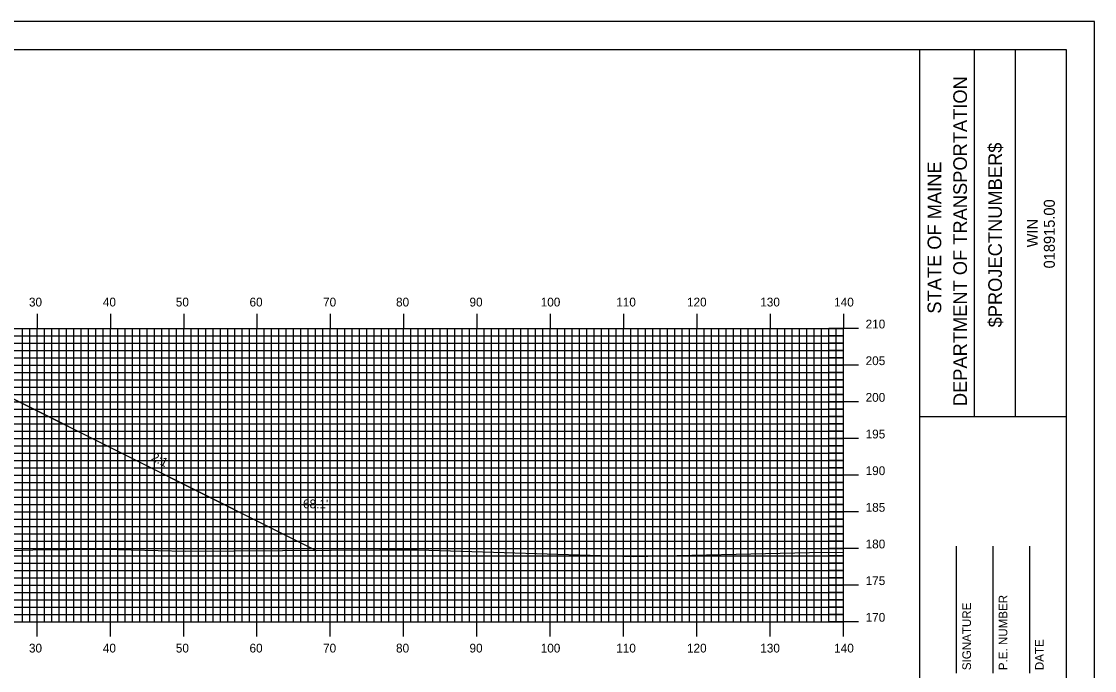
# Model space of a CAD drawing. Extents: x 1809013 to 1809356, y 442591 to 442811.
# Drawn here: x 1809206.2 to 1809352.5, y 442722 to 442810.5 of the extents above; entities that cross this region are included whole.
import ezdxf

# ---------------------------------------------------------------- set-up
doc = ezdxf.new("R2010")
doc.units = 0
for name, color, linetype in [('ANNOTATION', 7, 'Continuous'), ('BORDER', 7, 'Continuous'), ('D_Roadway_Centerline', 7, 'Continuous'), ('D_Roadway_SlopeLines', 7, 'Continuous'), ('D_Text_Standard', 7, 'Continuous'), ('H_V ANNOTATION', 7, 'Continuous'), ('MAJOR', 7, 'Continuous'), ('MINOR', 7, 'Continuous'), ('PLOT BOUNDARY', 7, 'Continuous'), ('S_Roadway_Centerline', 7, 'Continuous')]:
    doc.layers.add(name, color=color, linetype=linetype)

msp = doc.modelspace()

# ---------------------------------------------------------------- linework, layer by layer
at = {"layer": 'BORDER'}
for p, q in [((1809328.72, 442596.67), (1809328.72, 442806.67)), ((1809336.18, 442756.66), (1809336.18, 442806.66)), ((1809341.77, 442756.66), (1809341.77, 442806.66)), ((1809328.73, 442756.65), (1809348.72, 442756.65)), ((1809333.72, 442721.67), (1809333.72, 442738.97)), ((1809338.72, 442721.67), (1809338.72, 442738.97)), ((1809343.72, 442721.67), (1809343.72, 442738.97))]:
    msp.add_line(p, q, dxfattribs=at)
msp.add_lwpolyline([(1809028.72, 442596.67), (1809348.72, 442596.67), (1809348.72, 442806.67), (1809028.72, 442806.67)], close=True, dxfattribs=at)
at = {"layer": 'D_Roadway_Centerline'}
msp.add_lwpolyline([(1809110.51, 442738.65), (1809150.57, 442758.68), (1809155.32, 442761.06), (1809158.32, 442761.18), (1809166.32, 442761.5), (1809178.32, 442761.62), (1809190.32, 442761.38), (1809198.32, 442761.06), (1809201.32, 442760.94), (1809206.07, 442758.57), (1809246.41, 442738.4)], dxfattribs=at)
at = {"layer": 'D_Roadway_SlopeLines'}
msp.add_lwpolyline([(1809201.32, 442760.94), (1809246.41, 442738.4)], dxfattribs=at)
at = {"layer": 'MAJOR'}
for p, q in [((1809208.32, 442770.67), (1809208.32, 442768.67)), ((1809218.32, 442770.67), (1809218.32, 442768.67)), ((1809228.32, 442770.67), (1809228.32, 442768.67)), ((1809238.32, 442770.67), (1809238.32, 442768.67)), ((1809248.32, 442770.67), (1809248.32, 442768.67)), ((1809258.32, 442770.67), (1809258.32, 442768.67)), ((1809268.32, 442770.67), (1809268.32, 442768.67)), ((1809278.32, 442770.67), (1809278.32, 442768.67)), ((1809288.32, 442770.67), (1809288.32, 442768.67)), ((1809298.32, 442770.67), (1809298.32, 442768.67)), ((1809308.32, 442770.67), (1809308.32, 442768.67)), ((1809318.32, 442770.67), (1809318.32, 442768.67)), ((1809038.32, 442768.67), (1809318.32, 442768.67)), ((1809038.32, 442768.67), (1809318.32, 442768.67)), ((1809208.32, 442728.67), (1809208.32, 442768.67)), ((1809218.32, 442728.67), (1809218.32, 442768.67)), ((1809228.32, 442728.67), (1809228.32, 442768.67)), ((1809238.32, 442728.67), (1809238.32, 442768.67)), ((1809248.32, 442728.67), (1809248.32, 442768.67)), ((1809258.32, 442728.67), (1809258.32, 442768.67)), ((1809268.32, 442728.67), (1809268.32, 442768.67)), ((1809278.32, 442728.67), (1809278.32, 442768.67)), ((1809288.32, 442728.67), (1809288.32, 442768.67)), ((1809298.32, 442728.67), (1809298.32, 442768.67)), ((1809308.32, 442728.67), (1809308.32, 442768.67)), ((1809320.33, 442768.67), (1809316.32, 442768.67)), ((1809318.32, 442728.67), (1809318.32, 442768.67)), ((1809318.32, 442728.67), (1809318.32, 442768.67)), ((1809038.32, 442763.67), (1809318.32, 442763.67)), ((1809320.33, 442763.67), (1809316.32, 442763.67)), ((1809038.32, 442758.67), (1809318.32, 442758.67)), ((1809320.33, 442758.67), (1809316.32, 442758.67)), ((1809038.32, 442753.67), (1809318.32, 442753.67)), ((1809320.33, 442753.67), (1809316.32, 442753.67)), ((1809038.32, 442748.67), (1809318.32, 442748.67)), ((1809320.33, 442748.67), (1809316.32, 442748.67)), ((1809038.32, 442743.67), (1809318.32, 442743.67)), ((1809320.33, 442743.67), (1809316.32, 442743.67)), ((1809038.32, 442738.67), (1809318.32, 442738.67)), ((1809320.33, 442738.67), (1809316.32, 442738.67)), ((1809038.32, 442733.67), (1809318.32, 442733.67)), ((1809320.33, 442733.67), (1809316.32, 442733.67)), ((1809038.32, 442728.67), (1809318.32, 442728.67)), ((1809038.32, 442728.67), (1809318.32, 442728.67)), ((1809208.32, 442726.66), (1809208.32, 442728.67)), ((1809218.32, 442726.66), (1809218.32, 442728.67)), ((1809228.32, 442726.66), (1809228.32, 442728.67)), ((1809238.32, 442726.66), (1809238.32, 442728.67)), ((1809248.32, 442726.66), (1809248.32, 442728.67)), ((1809258.32, 442726.66), (1809258.32, 442728.67)), ((1809268.32, 442726.66), (1809268.32, 442728.67)), ((1809278.32, 442726.66), (1809278.32, 442728.67)), ((1809288.32, 442726.66), (1809288.32, 442728.67)), ((1809298.32, 442726.66), (1809298.32, 442728.67)), ((1809308.32, 442726.66), (1809308.32, 442728.67)), ((1809320.33, 442728.67), (1809316.32, 442728.67)), ((1809318.32, 442726.66), (1809318.32, 442728.67))]:
    msp.add_line(p, q, dxfattribs=at)
at = {"layer": 'MINOR'}
for p, q in [((1809206.32, 442728.67), (1809206.32, 442768.67)), ((1809207.32, 442728.67), (1809207.32, 442768.67)), ((1809209.32, 442728.67), (1809209.32, 442768.67)), ((1809210.32, 442728.67), (1809210.32, 442768.67)), ((1809211.32, 442728.67), (1809211.32, 442768.67)), ((1809212.32, 442728.67), (1809212.32, 442768.67)), ((1809213.32, 442728.67), (1809213.32, 442768.67)), ((1809214.32, 442728.67), (1809214.32, 442768.67)), ((1809215.32, 442728.67), (1809215.32, 442768.67)), ((1809216.32, 442728.67), (1809216.32, 442768.67)), ((1809217.32, 442728.67), (1809217.32, 442768.67)), ((1809219.32, 442728.67), (1809219.32, 442768.67)), ((1809220.32, 442728.67), (1809220.32, 442768.67)), ((1809221.32, 442728.67), (1809221.32, 442768.67)), ((1809222.32, 442728.67), (1809222.32, 442768.67)), ((1809223.32, 442728.67), (1809223.32, 442768.67)), ((1809224.32, 442728.67), (1809224.32, 442768.67)), ((1809225.32, 442728.67), (1809225.32, 442768.67)), ((1809226.32, 442728.67), (1809226.32, 442768.67)), ((1809227.32, 442728.67), (1809227.32, 442768.67)), ((1809229.32, 442728.67), (1809229.32, 442768.67)), ((1809230.32, 442728.67), (1809230.32, 442768.67)), ((1809231.32, 442728.67), (1809231.32, 442768.67)), ((1809232.32, 442728.67), (1809232.32, 442768.67)), ((1809233.32, 442728.67), (1809233.32, 442768.67)), ((1809234.32, 442728.67), (1809234.32, 442768.67)), ((1809235.32, 442728.67), (1809235.32, 442768.67)), ((1809236.32, 442728.67), (1809236.32, 442768.67)), ((1809237.32, 442728.67), (1809237.32, 442768.67)), ((1809239.32, 442728.67), (1809239.32, 442768.67)), ((1809240.32, 442728.67), (1809240.32, 442768.67)), ((1809241.32, 442728.67), (1809241.32, 442768.67)), ((1809242.32, 442728.67), (1809242.32, 442768.67)), ((1809243.32, 442728.67), (1809243.32, 442768.67)), ((1809244.32, 442728.67), (1809244.32, 442768.67)), ((1809245.32, 442728.67), (1809245.32, 442768.67)), ((1809246.32, 442728.67), (1809246.32, 442768.67)), ((1809247.32, 442728.67), (1809247.32, 442768.67)), ((1809249.32, 442728.67), (1809249.32, 442768.67)), ((1809250.32, 442728.67), (1809250.32, 442768.67)), ((1809251.32, 442728.67), (1809251.32, 442768.67)), ((1809252.32, 442728.67), (1809252.32, 442768.67)), ((1809253.32, 442728.67), (1809253.32, 442768.67)), ((1809254.32, 442728.67), (1809254.32, 442768.67)), ((1809255.32, 442728.67), (1809255.32, 442768.67)), ((1809256.32, 442728.67), (1809256.32, 442768.67)), ((1809257.32, 442728.67), (1809257.32, 442768.67)), ((1809259.32, 442728.67), (1809259.32, 442768.67)), ((1809260.32, 442728.67), (1809260.32, 442768.67)), ((1809261.32, 442728.67), (1809261.32, 442768.67)), ((1809262.32, 442728.67), (1809262.32, 442768.67)), ((1809263.32, 442728.67), (1809263.32, 442768.67)), ((1809264.32, 442728.67), (1809264.32, 442768.67)), ((1809265.32, 442728.67), (1809265.32, 442768.67)), ((1809266.32, 442728.67), (1809266.32, 442768.67)), ((1809267.32, 442728.67), (1809267.32, 442768.67)), ((1809269.32, 442728.67), (1809269.32, 442768.67)), ((1809270.32, 442728.67), (1809270.32, 442768.67)), ((1809271.32, 442728.67), (1809271.32, 442768.67)), ((1809272.32, 442728.67), (1809272.32, 442768.67)), ((1809273.32, 442728.67), (1809273.32, 442768.67)), ((1809274.32, 442728.67), (1809274.32, 442768.67)), ((1809275.32, 442728.67), (1809275.32, 442768.67)), ((1809276.32, 442728.67), (1809276.32, 442768.67)), ((1809277.32, 442728.67), (1809277.32, 442768.67)), ((1809279.32, 442728.67), (1809279.32, 442768.67)), ((1809280.32, 442728.67), (1809280.32, 442768.67)), ((1809281.32, 442728.67), (1809281.32, 442768.67)), ((1809282.32, 442728.67), (1809282.32, 442768.67)), ((1809283.32, 442728.67), (1809283.32, 442768.67)), ((1809284.32, 442728.67), (1809284.32, 442768.67)), ((1809285.32, 442728.67), (1809285.32, 442768.67)), ((1809286.32, 442728.67), (1809286.32, 442768.67)), ((1809287.32, 442728.67), (1809287.32, 442768.67)), ((1809289.32, 442728.67), (1809289.32, 442768.67)), ((1809290.32, 442728.67), (1809290.32, 442768.67)), ((1809291.32, 442728.67), (1809291.32, 442768.67)), ((1809292.32, 442728.67), (1809292.32, 442768.67)), ((1809293.32, 442728.67), (1809293.32, 442768.67)), ((1809294.32, 442728.67), (1809294.32, 442768.67)), ((1809295.32, 442728.67), (1809295.32, 442768.67)), ((1809296.32, 442728.67), (1809296.32, 442768.67)), ((1809297.32, 442728.67), (1809297.32, 442768.67)), ((1809299.32, 442728.67), (1809299.32, 442768.67)), ((1809300.32, 442728.67), (1809300.32, 442768.67)), ((1809301.32, 442728.67), (1809301.32, 442768.67)), ((1809302.32, 442728.67), (1809302.32, 442768.67)), ((1809303.32, 442728.67), (1809303.32, 442768.67)), ((1809304.32, 442728.67), (1809304.32, 442768.67)), ((1809305.32, 442728.67), (1809305.32, 442768.67)), ((1809306.32, 442728.67), (1809306.32, 442768.67)), ((1809307.32, 442728.67), (1809307.32, 442768.67)), ((1809309.32, 442728.67), (1809309.32, 442768.67)), ((1809310.32, 442728.67), (1809310.32, 442768.67)), ((1809311.32, 442728.67), (1809311.32, 442768.67)), ((1809312.32, 442728.67), (1809312.32, 442768.67)), ((1809313.32, 442728.67), (1809313.32, 442768.67)), ((1809314.32, 442728.67), (1809314.32, 442768.67)), ((1809315.32, 442728.67), (1809315.32, 442768.67)), ((1809316.32, 442728.67), (1809316.32, 442768.67)), ((1809317.32, 442728.67), (1809317.32, 442768.67)), ((1809038.32, 442767.67), (1809318.32, 442767.67)), ((1809318.32, 442767.67), (1809316.32, 442767.67)), ((1809038.32, 442766.67), (1809318.32, 442766.67)), ((1809038.32, 442765.67), (1809318.32, 442765.67)), ((1809318.32, 442766.67), (1809316.32, 442766.67)), ((1809318.32, 442765.67), (1809316.32, 442765.67)), ((1809038.32, 442764.67), (1809318.32, 442764.67)), ((1809318.32, 442764.67), (1809316.32, 442764.67)), ((1809038.32, 442762.67), (1809318.32, 442762.67)), ((1809318.32, 442762.67), (1809316.32, 442762.67)), ((1809038.32, 442761.67), (1809318.32, 442761.67)), ((1809318.32, 442761.67), (1809316.32, 442761.67)), ((1809038.32, 442760.67), (1809318.32, 442760.67)), ((1809038.32, 442759.67), (1809318.32, 442759.67)), ((1809318.32, 442760.67), (1809316.32, 442760.67)), ((1809318.32, 442759.67), (1809316.32, 442759.67)), ((1809038.32, 442757.67), (1809318.32, 442757.67)), ((1809318.32, 442757.67), (1809316.32, 442757.67)), ((1809038.32, 442756.67), (1809318.32, 442756.67)), ((1809038.32, 442755.67), (1809318.32, 442755.67)), ((1809318.32, 442756.67), (1809316.32, 442756.67)), ((1809318.32, 442755.67), (1809316.32, 442755.67)), ((1809038.32, 442754.67), (1809318.32, 442754.67)), ((1809318.32, 442754.67), (1809316.32, 442754.67)), ((1809038.32, 442752.67), (1809318.32, 442752.67)), ((1809318.32, 442752.67), (1809316.32, 442752.67)), ((1809038.32, 442751.67), (1809318.32, 442751.67)), ((1809318.32, 442751.67), (1809316.32, 442751.67)), ((1809038.32, 442750.67), (1809318.32, 442750.67)), ((1809038.32, 442749.67), (1809318.32, 442749.67)), ((1809318.32, 442750.67), (1809316.32, 442750.67)), ((1809318.32, 442749.67), (1809316.32, 442749.67)), ((1809038.32, 442747.67), (1809318.32, 442747.67)), ((1809038.32, 442746.67), (1809318.32, 442746.67)), ((1809318.32, 442747.67), (1809316.32, 442747.67)), ((1809318.32, 442746.67), (1809316.32, 442746.67)), ((1809038.32, 442745.67), (1809318.32, 442745.67)), ((1809318.32, 442745.67), (1809316.32, 442745.67)), ((1809038.32, 442744.67), (1809318.32, 442744.67)), ((1809318.32, 442744.67), (1809316.32, 442744.67)), ((1809038.32, 442742.67), (1809318.32, 442742.67)), ((1809318.32, 442742.67), (1809316.32, 442742.67)), ((1809038.32, 442741.67), (1809318.32, 442741.67)), ((1809038.32, 442740.67), (1809318.32, 442740.67)), ((1809318.32, 442741.67), (1809316.32, 442741.67)), ((1809318.32, 442740.67), (1809316.32, 442740.67)), ((1809038.32, 442739.67), (1809318.32, 442739.67)), ((1809318.32, 442739.67), (1809316.32, 442739.67)), ((1809038.32, 442737.67), (1809318.32, 442737.67)), ((1809318.32, 442737.67), (1809316.32, 442737.67)), ((1809038.32, 442736.67), (1809318.32, 442736.67)), ((1809318.32, 442736.67), (1809316.32, 442736.67)), ((1809038.32, 442735.67), (1809318.32, 442735.67)), ((1809318.32, 442735.67), (1809316.32, 442735.67)), ((1809038.32, 442734.67), (1809318.32, 442734.67)), ((1809318.32, 442734.67), (1809316.32, 442734.67)), ((1809038.32, 442732.67), (1809318.32, 442732.67)), ((1809318.32, 442732.67), (1809316.32, 442732.67)), ((1809038.32, 442731.67), (1809318.32, 442731.67)), ((1809038.32, 442730.67), (1809318.32, 442730.67)), ((1809318.32, 442731.67), (1809316.32, 442731.67)), ((1809318.32, 442730.67), (1809316.32, 442730.67)), ((1809038.32, 442729.67), (1809318.32, 442729.67)), ((1809318.32, 442729.67), (1809316.32, 442729.67))]:
    msp.add_line(p, q, dxfattribs=at)
at = {"layer": 'PLOT BOUNDARY'}
msp.add_lwpolyline([(1809012.54, 442590.55), (1809352.54, 442590.55), (1809352.54, 442810.55), (1809012.54, 442810.55)], close=True, dxfattribs=at)
at = {"layer": 'S_Roadway_Centerline'}
msp.add_lwpolyline([(1809197.67, 442738.14), (1809207.77, 442738.48), (1809217.5, 442738.56), (1809228.53, 442738.28), (1809255.05, 442738.46), (1809259.04, 442738.48), (1809260.31, 442738.46), (1809289.6, 442737.57), (1809313.65, 442738.09), (1809318.32, 442738.18)], dxfattribs=at)

# ---------------------------------------------------------------- texts
at = {"layer": 'ANNOTATION'}
msp.add_text('2:1', height=1.2, rotation=333.4349, dxfattribs=at).set_placement((1809223.8, 442750.74))
at = {"layer": 'BORDER'}
for s, height, p in [('DEPARTMENT OF TRANSPORTATION', 1.8635, (1809335.14, 442758.08)), ('$PROJECTNUMBER$', 1.8635, (1809339.91, 442768.82)), ('STATE OF MAINE', 1.8635, (1809331.63, 442770.69)), ('018915.00', 1.491, (1809347.12, 442776.86)), ('WIN', 1.491, (1809344.8, 442779.73)), ('P.E. NUMBER', 1.1811, (1809340.65, 442722.06)), ('SIGNATURE', 1.181, (1809335.69, 442722.06)), ('DATE', 1.181, (1809345.61, 442722.06))]:
    msp.add_text(s, height=height, rotation=90, dxfattribs=at).set_placement(p)
at = {"layer": 'D_Text_Standard'}
msp.add_text("68.1'", height=1.2, dxfattribs=at).set_placement((1809244.6, 442744.14))
at = {"layer": 'H_V ANNOTATION'}
for s, p in [('30', (1809207.22, 442771.67)), ('40', (1809217.3, 442771.67)), ('50', (1809227.25, 442771.67)), ('60', (1809237.3, 442771.67)), ('70', (1809247.33, 442771.67)), ('80', (1809257.28, 442771.67)), ('90', (1809267.3, 442771.67)), ('100', (1809277.01, 442771.67)), ('110', (1809287.31, 442771.67)), ('120', (1809296.96, 442771.67)), ('130', (1809306.95, 442771.67)), ('140', (1809317.03, 442771.67)), ('210', (1809321.32, 442768.67)), ('205', (1809321.32, 442763.67)), ('200', (1809321.32, 442758.67)), ('195', (1809321.32, 442753.67)), ('190', (1809321.32, 442748.67)), ('185', (1809321.32, 442743.67)), ('180', (1809321.32, 442738.67)), ('175', (1809321.32, 442733.67)), ('170', (1809321.32, 442728.67)), ('30', (1809207.22, 442724.47)), ('40', (1809217.3, 442724.47)), ('50', (1809227.25, 442724.47)), ('60', (1809237.3, 442724.47)), ('70', (1809247.33, 442724.47)), ('80', (1809257.28, 442724.47)), ('90', (1809267.3, 442724.47)), ('100', (1809277.01, 442724.47)), ('110', (1809287.31, 442724.47)), ('120', (1809296.96, 442724.47)), ('130', (1809306.95, 442724.47)), ('140', (1809317.03, 442724.47))]:
    msp.add_text(s, height=1.2, dxfattribs=at).set_placement(p)

doc.saveas('drawing.dxf')
